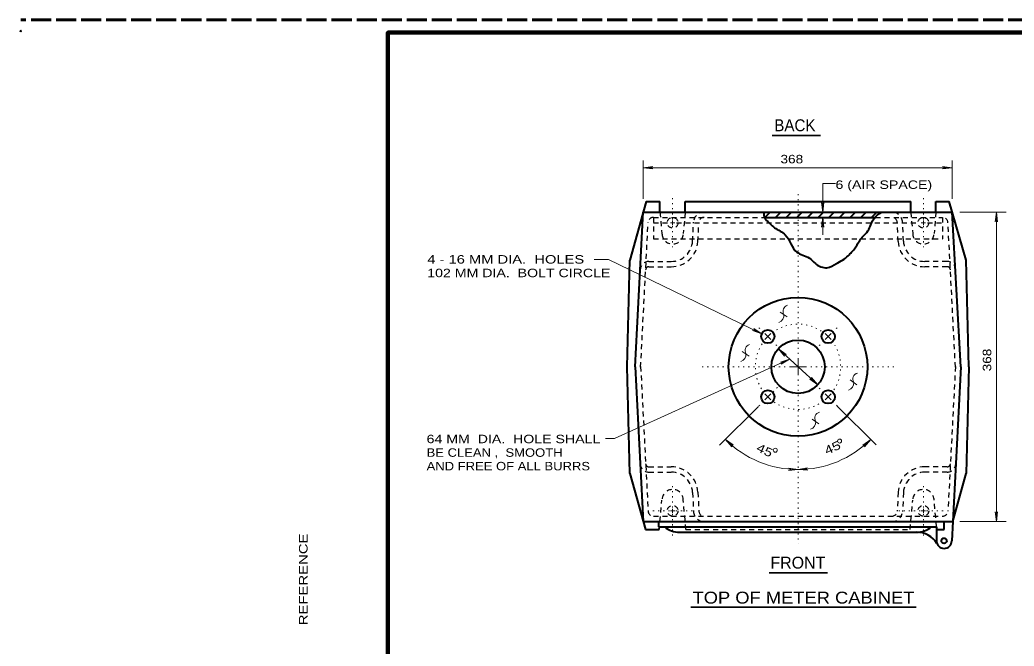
# Model space of a CAD drawing. Extents: x 312583 to 312853, y 144419 to 144586.
# Drawn here: x 312583.5 to 312672.7, y 144530 to 144586.2 of the extents above; entities that cross this region are included whole.
import ezdxf
from ezdxf.enums import TextEntityAlignment as Align

# ---------------------------------------------------------------- set-up
doc = ezdxf.new("R2010")
doc.units = 0
doc.header["$LTSCALE"] = 0.3
doc.header["$PDMODE"] = 32
doc.header["$PDSIZE"] = 0.15
for name, pattern in [('DOTTED', [1.5, 0.3, -1.2]), ('LONG_DASHED', [7.5, 6, -1.5]), ('SHORT_DASHED', [2.7, 1.5, -1.2])]:
    doc.linetypes.add(name, pattern=pattern)
doc.layers.add('1', color=7, linetype='Continuous', lineweight=13)

msp = doc.modelspace()

# ---------------------------------------------------------------- linework, layer by layer
at = {"layer": '1', "linetype": 'LONG_DASHED', "lineweight": 60}
msp.add_line((312851.75, 144586.2246), (312583.526, 144586.2246), dxfattribs=at)
msp.add_line((312851.75, 144586.2246), (312583.526, 144586.2246), dxfattribs=at)
at = {"layer": '1', "lineweight": 35}
for p, q in [((312651.0203, 144575.8458), (312655.3519, 144575.8458)), ((312650.7519, 144536.5618), (312655.9883, 144536.5618)), ((312643.711, 144533.4798), (312663.9595, 144533.4798))]:
    msp.add_line(p, q, dxfattribs=at)
at = {"layer": '1'}
for p, q in [((312639.4359, 144570.1648), (312639.4359, 144573.6071)), ((312667.1893, 144570.1648), (312667.1893, 144573.6071)), ((312639.4359, 144572.9401), (312640.3023, 144573.0474)), ((312639.4359, 144572.9401), (312667.1893, 144572.9401)), ((312639.4359, 144572.9401), (312640.3023, 144572.8328)), ((312640.3023, 144573.0474), (312640.0263, 144572.9401)), ((312640.3023, 144572.8328), (312640.0263, 144572.9401)), ((312666.3229, 144573.0474), (312666.5989, 144572.9401)), ((312667.1893, 144572.9401), (312666.3229, 144573.0474)), ((312666.3229, 144572.8328), (312666.5989, 144572.9401)), ((312667.1893, 144572.9401), (312666.3229, 144572.8328)), ((312655.5513, 144571.5218), (312656.6859, 144571.5218)), ((312655.5513, 144568.9611), (312655.5513, 144571.5218)), ((312655.4439, 144569.8274), (312655.5513, 144569.5514)), ((312655.5513, 144568.9611), (312655.4439, 144569.8274)), ((312655.6586, 144569.8274), (312655.5513, 144569.5514)), ((312655.5513, 144568.9611), (312655.6586, 144569.8274)), ((312667.8639, 144568.9611), (312672.0324, 144568.9611)), ((312671.1565, 144568.9611), (312671.0492, 144568.0948)), ((312671.1565, 144541.1694), (312671.1565, 144568.9611)), ((312671.1565, 144568.9611), (312671.2639, 144568.0948)), ((312642.0733, 144568.0028), (312641.8816, 144568.0028)), ((312642.0733, 144568.0028), (312642.0733, 144568.1944)), ((312642.0733, 144568.0028), (312642.2649, 144568.0028)), ((312642.0733, 144568.0028), (312642.0733, 144567.8111)), ((312655.5513, 144568.4858), (312655.4439, 144567.6194)), ((312655.4439, 144567.6194), (312655.5513, 144567.8954)), ((312655.5513, 144566.9141), (312655.5513, 144568.4858)), ((312655.5513, 144568.4858), (312655.6586, 144567.6194)), ((312655.6586, 144567.6194), (312655.5513, 144567.8954)), ((312664.5979, 144568.0028), (312664.4063, 144568.0028)), ((312664.5979, 144568.0028), (312664.5979, 144568.1944)), ((312664.5979, 144568.0028), (312664.7896, 144568.0028)), ((312664.5979, 144568.0028), (312664.5979, 144567.8111)), ((312671.0492, 144568.0948), (312671.1565, 144568.3708)), ((312671.2639, 144568.0948), (312671.1565, 144568.3708)), ((312636.3079, 144564.7061), (312635.0276, 144564.7061)), ((312650.0849, 144558.0361), (312636.3079, 144564.7061)), ((312651.7409, 144559.9681), (312652.3466, 144559.5464)), ((312649.2569, 144558.3198), (312649.5559, 144558.2968)), ((312650.0849, 144558.0361), (312649.2569, 144558.3198)), ((312649.3566, 144558.5114), (312649.5559, 144558.2968)), ((312650.0849, 144558.0361), (312649.3566, 144558.5114)), ((312650.6216, 144557.7754), (312650.3533, 144558.0514)), ((312650.6216, 144557.7754), (312650.8976, 144558.0514)), ((312656.0419, 144557.7754), (312655.7736, 144558.0514)), ((312656.0419, 144557.7754), (312656.3179, 144558.0514)), ((312650.6216, 144557.7754), (312650.3533, 144557.5071)), ((312650.6216, 144557.7754), (312650.8976, 144557.5071)), ((312656.0419, 144557.7754), (312655.7736, 144557.5071)), ((312656.0419, 144557.7754), (312656.3179, 144557.5071)), ((312648.3293, 144556.4491), (312648.9349, 144556.0274)), ((312651.5723, 144556.6868), (312655.0989, 144553.4438)), ((312651.5723, 144556.6868), (312652.1319, 144556.0274)), ((312651.5723, 144556.6868), (312652.2776, 144556.1808)), ((312652.1319, 144556.0274), (312652.0016, 144556.2881)), ((312652.2776, 144556.1808), (312652.0016, 144556.2881)), ((312652.5766, 144555.7591), (312636.8446, 144548.6138)), ((312652.5766, 144555.7591), (312651.7486, 144555.4984)), ((312651.7486, 144555.4984), (312652.0399, 144555.5214)), ((312652.5766, 144555.7591), (312651.8329, 144555.3068)), ((312651.8329, 144555.3068), (312652.0399, 144555.5214)), ((312653.3356, 144555.0691), (312653.3356, 144555.8358)), ((312653.3356, 144555.0691), (312652.5689, 144555.0691)), ((312653.3356, 144555.0691), (312654.1023, 144555.0691)), ((312653.3356, 144555.0691), (312653.3356, 144554.3024)), ((312654.3859, 144553.9574), (312654.6619, 144553.8424)), ((312655.0989, 144553.4438), (312654.3859, 144553.9574)), ((312654.5316, 144554.1108), (312654.6619, 144553.8424)), ((312655.0989, 144553.4438), (312654.5316, 144554.1108)), ((312658.0123, 144553.8884), (312658.6179, 144553.4591)), ((312650.6216, 144552.3551), (312650.3533, 144552.6311)), ((312650.6216, 144552.3551), (312650.8976, 144552.6311)), ((312656.0419, 144552.3551), (312655.7736, 144552.6311)), ((312656.0419, 144552.3551), (312656.3179, 144552.6311)), ((312650.6216, 144552.3551), (312650.3533, 144552.0868)), ((312650.6216, 144552.3551), (312650.8976, 144552.0868)), ((312656.0419, 144552.3551), (312655.7736, 144552.0868)), ((312656.0419, 144552.3551), (312656.3179, 144552.0868)), ((312649.7706, 144551.5041), (312646.2823, 144548.0158)), ((312656.8623, 144551.5348), (312660.3583, 144548.0464)), ((312654.6006, 144550.3694), (312655.2063, 144549.9401)), ((312636.8446, 144548.6138), (312636.0523, 144548.6138)), ((312646.8113, 144548.5448), (312647.3863, 144547.8854)), ((312646.8113, 144548.5448), (312647.5243, 144548.0464)), ((312647.3863, 144547.8854), (312647.2483, 144548.1538)), ((312647.5243, 144548.0464), (312647.2483, 144548.1538)), ((312659.8599, 144548.5448), (312659.1623, 144548.0234)), ((312659.1623, 144548.0234), (312659.4306, 144548.1384)), ((312659.8599, 144548.5448), (312659.3079, 144547.8701)), ((312659.3079, 144547.8701), (312659.4306, 144548.1384)), ((312652.4693, 144545.9764), (312652.7453, 144545.8614)), ((312653.3356, 144545.8461), (312652.4693, 144545.9764)), ((312652.4693, 144545.7618), (312652.7453, 144545.8614)), ((312653.3356, 144545.8461), (312652.4693, 144545.7618)), ((312653.3356, 144545.8461), (312654.1943, 144545.9918)), ((312653.3356, 144545.8461), (312654.2019, 144545.7771)), ((312654.1943, 144545.9918), (312653.9259, 144545.8768)), ((312654.2019, 144545.7771), (312653.9259, 144545.8768)), ((312642.0733, 144542.1278), (312641.8816, 144542.1278)), ((312642.0733, 144542.1278), (312642.0733, 144542.3194)), ((312642.0733, 144542.1278), (312642.2649, 144542.1278)), ((312642.0733, 144542.1278), (312642.0733, 144541.9361)), ((312664.5979, 144542.1278), (312664.4063, 144542.1278)), ((312664.5979, 144542.1278), (312664.5979, 144542.3194)), ((312664.5979, 144542.1278), (312664.7896, 144542.1278)), ((312664.5979, 144542.1278), (312664.5979, 144541.9361)), ((312671.0492, 144542.0358), (312671.1565, 144541.7598)), ((312671.1565, 144541.1694), (312671.0492, 144542.0358)), ((312671.2639, 144542.0358), (312671.1565, 144541.7598)), ((312671.1565, 144541.1694), (312671.2639, 144542.0358)), ((312667.8639, 144541.1694), (312672.0324, 144541.1694))]:
    msp.add_line(p, q, dxfattribs=at)
at = {"layer": '1', "linetype": 'DOTTED'}
for p, q in [((312653.3356, 144556.2191), (312653.3356, 144570.8164)), ((312642.0733, 144568.2941), (312642.0733, 144570.2108)), ((312664.5979, 144568.2941), (312664.5979, 144570.2108)), ((312642.0733, 144567.7191), (312642.0733, 144565.8024)), ((312664.5979, 144567.7191), (312664.5979, 144565.8024)), ((312650.2153, 144558.1818), (312649.7553, 144558.6494)), ((312656.4483, 144558.1818), (312657.0156, 144558.7491)), ((312651.0279, 144557.3691), (312651.4419, 144556.9628)), ((312655.6356, 144557.3691), (312655.1603, 144556.8938)), ((312652.1856, 144555.0691), (312644.5189, 144555.0691)), ((312654.4856, 144555.0691), (312662.1523, 144555.0691)), ((312653.3356, 144553.9191), (312653.3356, 144539.1914)), ((312651.0816, 144552.8151), (312651.5186, 144553.2521)), ((312655.6356, 144552.7614), (312655.2063, 144553.1908)), ((312650.2153, 144551.9488), (312649.7706, 144551.5041)), ((312656.4483, 144551.9488), (312656.8623, 144551.5424)), ((312642.0733, 144542.4191), (312642.0733, 144544.3358)), ((312664.5979, 144542.4191), (312664.5979, 144544.3358)), ((312641.7896, 144542.1278), (312640.1029, 144542.1278)), ((312642.0733, 144541.8441), (312642.0733, 144539.9274)), ((312642.3646, 144542.1278), (312644.1969, 144542.1278)), ((312664.3066, 144542.1278), (312662.3899, 144542.1278)), ((312664.5979, 144541.8441), (312664.5979, 144539.9274)), ((312664.8816, 144542.1278), (312666.5376, 144542.1278))]:
    msp.add_line(p, q, dxfattribs=at)
at = {"layer": '1', "lineweight": 40}
for p, q in [((312639.7043, 144569.9194), (312638.2399, 144564.6524)), ((312639.7043, 144569.9194), (312640.9386, 144569.9194)), ((312640.9386, 144568.9611), (312640.9386, 144569.9194)), ((312643.2003, 144569.9194), (312663.4633, 144569.9194)), ((312643.2003, 144568.9611), (312643.2003, 144569.9194)), ((312663.4633, 144568.9611), (312663.4633, 144569.9194)), ((312665.7249, 144569.9194), (312666.9133, 144569.9194)), ((312665.7249, 144568.9611), (312665.7249, 144569.9194)), ((312668.4313, 144564.6524), (312666.9133, 144569.9194)), ((312638.7229, 144555.0691), (312639.4359, 144568.9611)), ((312639.4359, 144568.9611), (312667.1893, 144568.9611)), ((312650.3456, 144568.4858), (312650.8286, 144568.9611)), ((312651.3039, 144568.4858), (312651.7869, 144568.9611)), ((312652.2623, 144568.4858), (312652.7453, 144568.9611)), ((312653.2206, 144568.4858), (312653.7036, 144568.9611)), ((312654.1789, 144568.4858), (312654.6619, 144568.9611)), ((312655.1373, 144568.4858), (312655.6203, 144568.9611)), ((312656.0956, 144568.4858), (312656.5786, 144568.9611)), ((312657.0539, 144568.4858), (312657.5369, 144568.9611)), ((312658.0123, 144568.4858), (312658.4953, 144568.9611)), ((312658.9706, 144568.4858), (312659.4536, 144568.9611)), ((312659.9289, 144568.4858), (312660.4119, 144568.9611)), ((312667.9483, 144555.0691), (312667.1893, 144568.9611)), ((312650.3456, 144568.4858), (312660.3046, 144568.4858)), ((312668.6689, 144555.0691), (312668.4313, 144564.6524)), ((312638.7229, 144555.0691), (312639.4359, 144541.1694)), ((312667.9483, 144555.0691), (312667.1433, 144539.4444)), ((312668.6689, 144555.0691), (312668.4313, 144545.4858)), ((312638.2399, 144545.4858), (312639.6353, 144540.4564)), ((312667.2276, 144541.1694), (312668.4313, 144545.4858)), ((312639.4359, 144541.1694), (312667.2276, 144541.1694)), ((312640.7929, 144541.1464), (312640.7929, 144540.6941)), ((312666.4686, 144540.4564), (312666.4686, 144541.1694)), ((312639.6353, 144540.4564), (312640.8773, 144540.4564)), ((312640.7929, 144540.6941), (312665.7709, 144540.6941)), ((312640.8773, 144540.4564), (312640.9003, 144540.6941)), ((312642.6866, 144540.2111), (312663.9846, 144540.2111)), ((312665.7709, 144540.6941), (312665.7709, 144539.4444)), ((312665.7709, 144540.4564), (312666.4686, 144540.4564))]:
    msp.add_line(p, q, dxfattribs=at)
at = {"layer": '1', "linetype": 'SHORT_DASHED', "lineweight": 25}
for p, q in [((312640.9386, 144568.9611), (312641.1149, 144567.0444)), ((312643.2003, 144568.9611), (312643.0316, 144567.0444)), ((312663.4633, 144568.9611), (312663.6396, 144567.0444)), ((312665.7249, 144568.9611), (312665.5563, 144567.0444)), ((312639.1983, 144555.0461), (312639.8729, 144568.0334)), ((312640.3483, 144568.4858), (312640.3483, 144566.5691)), ((312640.3483, 144568.4858), (312650.3456, 144568.4858)), ((312640.3483, 144568.0028), (312641.6823, 144568.0028)), ((312642.4106, 144568.0028), (312664.1993, 144568.0028)), ((312643.8673, 144566.3544), (312643.9516, 144568.0564)), ((312644.3426, 144566.3238), (312644.4269, 144568.0258)), ((312660.3046, 144568.4858), (312666.3229, 144568.4858)), ((312662.3286, 144566.3238), (312662.2366, 144568.0258)), ((312662.8039, 144566.3544), (312662.7196, 144568.0564)), ((312664.9736, 144568.0028), (312666.3229, 144568.0028)), ((312666.3229, 144568.4858), (312666.3229, 144566.5691)), ((312667.4729, 144555.0461), (312666.7983, 144568.0334)), ((312640.3483, 144566.5691), (312666.3229, 144566.5691)), ((312639.9343, 144564.5298), (312641.9506, 144564.5298)), ((312666.7293, 144564.5298), (312664.7206, 144564.5298)), ((312639.9343, 144564.0544), (312641.9506, 144564.0544)), ((312666.7293, 144564.0544), (312664.7206, 144564.0544)), ((312639.1983, 144555.0921), (312639.8729, 144542.1048)), ((312667.4729, 144555.0921), (312666.7983, 144542.1048)), ((312639.9343, 144546.0838), (312641.9506, 144546.0838)), ((312639.9343, 144545.6084), (312641.9506, 144545.6084)), ((312666.7293, 144546.0838), (312664.7206, 144546.0838)), ((312666.7293, 144545.6084), (312664.7206, 144545.6084)), ((312643.8673, 144543.7838), (312643.9516, 144542.0818)), ((312644.3426, 144543.8068), (312644.4269, 144542.1048)), ((312662.3286, 144543.8068), (312662.2366, 144542.1048)), ((312662.8039, 144543.7838), (312662.7196, 144542.0818)), ((312640.9386, 144541.1694), (312641.1149, 144543.0861)), ((312643.2693, 144540.4564), (312643.0316, 144543.0861)), ((312663.4019, 144540.4564), (312663.6396, 144543.0861)), ((312665.7709, 144540.6941), (312665.5563, 144543.0861)), ((312640.3483, 144541.6524), (312666.3229, 144541.6524)), ((312643.2693, 144540.4564), (312663.4019, 144540.4564))]:
    msp.add_line(p, q, dxfattribs=at)
at = {"layer": '1', "lineweight": 158}
msp.add_lwpolyline([(312616.5, 144423.1446), (312616.5, 144585.0846), (312849, 144585.0846)], dxfattribs=at)
at = {"layer": '1', "lineweight": 40}
msp.add_lwpolyline([(312638.2399, 144545.4858), (312638.0023, 144555.0691), (312638.2399, 144564.6524)], dxfattribs=at)
at = {"layer": '1', "linetype": 'SHORT_DASHED', "lineweight": 25}
for centre in [(312642.0733, 144568.0066), (312664.5941, 144568.0066), (312642.0733, 144542.1316), (312664.5941, 144542.1316)]:
    msp.add_circle(centre, 0.4792, dxfattribs=at)
at = {"layer": '1', "lineweight": 40}
for centre, radius in [((312653.3337, 144555.0691), 6.2292), ((312650.6235, 144557.7793), 0.599), ((312656.0439, 144557.7793), 0.599), ((312653.3337, 144555.0691), 2.3958), ((312650.6235, 144552.3589), 0.599), ((312656.0439, 144552.3589), 0.599), ((312666.4533, 144539.4444), 0.2396)]:
    msp.add_circle(centre, radius, dxfattribs=at)
at = {"layer": '1'}
for centre in [(312657.0652, 144548.4009), (312651.2903, 144547.5768)]:
    msp.add_circle(centre, 0.1797, dxfattribs=at)
at = {"layer": '1', "linetype": 'SHORT_DASHED', "lineweight": 25}
for centre, radius, start, end in [((312644.9064, 144568.0066), 0.9583, 90, 177.11172), ((312661.7609, 144568.0066), 0.9583, 2.88828, 90), ((312640.349, 144568.0066), 0.4792, 90, 177.03696), ((312644.9064, 144568.0066), 0.4792, 90, 177.11172), ((312661.7609, 144568.0066), 0.4792, 2.88828, 90), ((312666.3183, 144568.0066), 0.4792, 2.96304, 90), ((312642.0733, 144567.0483), 0.9583, 180, 0), ((312664.5941, 144567.0483), 0.9583, 180, 0), ((312641.9498, 144566.4484), 1.9167, 270, 357.13759), ((312641.9498, 144566.4484), 2.3958, 270, 357.13759), ((312664.7175, 144566.4484), 2.3958, 182.86241, 270), ((312664.7175, 144566.4484), 1.9167, 182.86241, 270), ((312639.9366, 144563.765), 0.7667, 90, 177.03906), ((312666.7308, 144563.765), 0.7667, 2.96094, 90), ((312639.9366, 144563.765), 0.2875, 90, 177.03906), ((312666.7308, 144563.765), 0.2875, 2.96094, 90), ((312639.9366, 144546.3732), 0.7667, 182.96094, 270), ((312639.9366, 144546.3732), 0.2875, 182.96094, 270), ((312666.7308, 144546.3732), 0.2875, 270, 357.03906), ((312666.7308, 144546.3732), 0.7667, 270, 357.03906), ((312641.9498, 144543.6899), 2.3958, 2.86241, 90), ((312641.9498, 144543.6899), 1.9167, 2.86241, 90), ((312664.7175, 144543.6899), 2.3958, 90, 177.13759), ((312664.7175, 144543.6899), 1.9167, 90, 177.13759), ((312642.0733, 144543.0899), 0.9583, 0, 180), ((312664.5941, 144543.0899), 0.9583, 0, 180), ((312640.349, 144542.1316), 0.4792, 182.96304, 270), ((312644.9064, 144542.1316), 0.9583, 182.88828, 270), ((312644.9064, 144542.1316), 0.4792, 182.88828, 270), ((312661.7609, 144542.1316), 0.4792, 270, 357.11172), ((312661.7609, 144542.1316), 0.9583, 270, 357.11172), ((312666.3183, 144542.1316), 0.4792, 270, 357.03696)]:
    msp.add_arc(centre, radius, start, end, dxfattribs=at)
at = {"layer": '1'}
for centre, radius, start, end in [((312652.5433, 144560.055), 0.5555, 104.98164, 210.86052), ((312651.3819, 144559.7075), 0.6875, 289.38376, 5.22592), ((312649.1336, 144556.536), 0.5555, 104.98164, 210.86052), ((312647.9722, 144556.1885), 0.6875, 289.38376, 5.22592), ((312658.8108, 144553.9715), 0.5555, 104.98164, 210.86052), ((312657.6494, 144553.624), 0.6875, 289.38376, 5.22592), ((312655.4011, 144550.4525), 0.5555, 104.98164, 210.86052), ((312654.2397, 144550.105), 0.6875, 289.38376, 5.22592), ((312653.3337, 144555.0691), 9.225, 225, 270), ((312653.3337, 144555.0691), 9.225, 270, 315.01684)]:
    msp.add_arc(centre, radius, start, end, dxfattribs=at)
at = {"layer": '1', "linetype": 'DOTTED'}
for start, end in [(56.92932, 123.4994), (147.52661, 213.80923), (327.28505, 33.3722), (236.00023, 301.94161)]:
    msp.add_arc((312653.3337, 144555.0691), 3.8333, start, end, dxfattribs=at)
at = {"layer": '1', "lineweight": 40}
for centre, radius, start, end in [((312642.6896, 144542.3222), 2.1073, 230.75329, 269.91814), ((312663.9778, 144542.3222), 2.1073, 270.08186, 309.24671), ((312663.9735, 144538.0418), 2.1732, 32.22812, 89.80783), ((312666.4533, 144539.4444), 0.6862, 180, 0)]:
    msp.add_arc(centre, radius, start, end, dxfattribs=at)
msp.add_spline([(312650.2613, 144568.9534), (312650.3609, 144568.4014), (312650.4146, 144568.3248), (312650.8209, 144567.9184), (312651.2273, 144567.5581), (312652.1933, 144566.9218), (312653.2129, 144565.3731), (312654.3553, 144564.8364), (312654.8919, 144564.3304), (312655.9346, 144563.9701), (312656.7779, 144564.3304), (312657.8436, 144565.0358), (312658.1503, 144565.3731), (312658.4799, 144565.7488), (312658.6869, 144566.1091), (312659.2696, 144566.8988), (312659.6989, 144567.4048), (312659.9289, 144567.9644), (312660.4426, 144568.6774), (312660.8719, 144568.9534)], degree=3, dxfattribs=at)
at = {"layer": '1'}
msp.add_point((312583.526, 144585.2246), dxfattribs=at)

# ---------------------------------------------------------------- texts
for s, width, p in [('BACK', 0.95, (312653.0522, 144576.2246)), ('TOP OF METER CABINET', 1.15, (312653.8249, 144533.8015))]:
    msp.add_text(s, height=1.07, dxfattribs=dict(at, width=width)).set_placement(p, align=Align.CENTER)
for s, width, p in [('368 ', 1.2, (312651.761, 144573.3417)), (' 6 (AIR SPACE)', 1.25, (312656.3457, 144571.0429)), ('4 - 16 MM DIA.  HOLES', 1.3, (312620.0368, 144564.336)), ('102 MM DIA.  BOLT CIRCLE', 1.25, (312620.0368, 144563.116)), ('64 MM  DIA.  HOLE SHALL', 1.25, (312619.9792, 144548.2052)), ('BE CLEAN ,  SMOOTH', 1.15, (312619.9792, 144546.9852)), ('AND FREE OF ALL BURRS', 1.15, (312619.9792, 144545.7652))]:
    msp.add_text(s, height=0.76, dxfattribs=dict(at, width=width)).set_placement(p)
for s, height, rotation, width, p in [('368 ', 0.76, 90, 1.2, (312670.6858, 144554.6577)), ('45', 0.76, 25, 1.3, (312655.9243, 144547.1441)), ('45', 0.76, 335, 1.3, (312649.5163, 144547.5377)), ('REFERENCE                                                              ', 0.7682, 90, 1.3, (312609.2854, 144531.8549))]:
    msp.add_text(s, height=height, rotation=rotation, dxfattribs=dict(at, width=width)).set_placement(p)
msp.add_text('FRONT', height=1.07, dxfattribs=at).set_placement((312653.3208, 144536.9406), align=Align.CENTER)

doc.saveas('drawing.dxf')
